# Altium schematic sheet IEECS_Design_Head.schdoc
size 309 x 223 mm; Symbol: Sheet-Symbol_A4; Device: Sheet-Symbol_A4; @Page Name: P1; @Create Date: 2022-10-18; @Page Count: 1; @Page No: 1; @Project Name: IEECS-Design-Head; @Schematic Name: Schematic1; @Update Date: 2022-10-18; Company: 嘉立创EDA; Page Size: A4; Version: V1.0
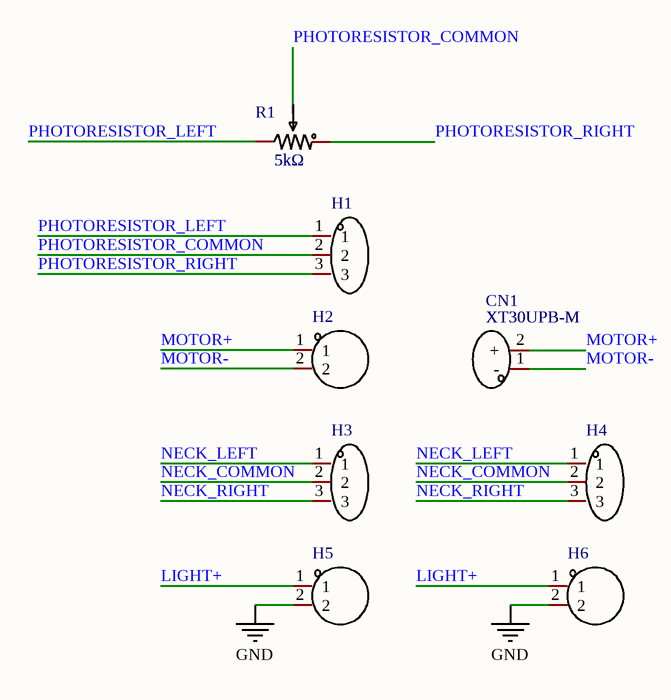
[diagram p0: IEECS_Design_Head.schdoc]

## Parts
CN1  XT30UPB-M  [CONN-TH_XT30UPB-M]
H1  HDR-M_2.54_1x3P  [Pin1X3]  (value not drawn)
H2  HDR-M_2.54_1x2P  [Pin1x2]  (value not drawn)
H3  HDR-M_2.54_1x3P  [Pin1X3]  (value not drawn)
H4  HDR-M_2.54_1x3P  [Pin1X3]  (value not drawn)
H5  HDR-M_2.54_1x2P  [Pin1x2]  (value not drawn)
H6  HDR-M_2.54_1x2P  [Pin1x2]  (value not drawn)
R1  5kΩ  [Slide_Res]

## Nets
GND: H5.2 H6.2
LIGHT+: H5.1 H6.1
MOTOR+: CN1.2(+) H2.1
MOTOR-: CN1.1(-) H2.2
NECK_COMMON: H3.2 H4.2
NECK_LEFT: H3.1 H4.1
NECK_RIGHT: H3.3 H4.3
PHOTORESISTOR_COMMON: H1.2 R1.2
PHOTORESISTOR_LEFT: H1.1 R1.3
PHOTORESISTOR_RIGHT: H1.3 R1.1

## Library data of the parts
CN1 = XT30UPB-M: Manufacturer: Changzhou Amass Elec; Convert to PCB: yes
H1 H3 H4 = HDR-M_2.54_1x3P: Symbol: PZ254V-11-03P_C2937625; Convert to PCB: yes
H2 H5 H6 = HDR-M_2.54_1x2P: Symbol: 210S-1*2P L=11.6MMGold-plated black; Convert to PCB: yes
R1 = 3362P-1-502: 阻值:5kΩ;精度:±10%;温度系数:±250ppm/;; Manufacturer: BOCHEN(博晨); Add into BOM: yes; Tolerance: ±10%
